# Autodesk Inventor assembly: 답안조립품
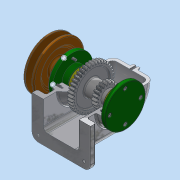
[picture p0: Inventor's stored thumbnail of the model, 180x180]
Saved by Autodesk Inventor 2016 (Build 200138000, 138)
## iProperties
Created: 2018-08
Part Number: 답안조립품
Material: 일반
Document SubType Name: Assembly
Designer: Administrator
Author: Administrator
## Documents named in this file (14)
- C:\Users\Administrator\Desktop\480811V1004\답안조립품.iam
- C:\Users\Administrator\Desktop\480811V1004\본체.ipt
- C:\Users\Administrator\Desktop\480811V1004\뒤커버.ipt
- C:\Users\Administrator\Desktop\480811V1004\볼트 M4.ipt
- C:\Users\Administrator\Desktop\480811V1004\베어링 6203.ipt
- C:\Users\Administrator\Desktop\480811V1004\축.ipt
- C:\Users\Administrator\Desktop\480811V1004\키 6x6x22.ipt
- C:\Users\Administrator\Desktop\480811V1004\스퍼기어.ipt
- C:\Users\Administrator\Desktop\480811V1004\앞커버.ipt
- C:\Users\Administrator\Desktop\480811V1004\부시.ipt
- C:\Users\Administrator\Desktop\480811V1004\오일 실 28 40 8.ipt
- C:\Users\Administrator\Desktop\480811V1004\V-벨트풀리.ipt
- C:\Users\Administrator\Desktop\480811V1004\키 5x5x18.ipt
- C:\Users\Administrator\Desktop\480811V1004\멈춤나사 M4.ipt
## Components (1 placed, 1 different names)
1. V-벨트풀리:1
